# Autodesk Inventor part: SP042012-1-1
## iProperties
Created: 2012-04
Part Number: SP042012-1-1
Material: PVC-U
Document SubType Name: Modeling
Designer: Administrator
Density: 1.4 g/cm^3
Mass: 303.761 g
Surface Area: 2103.56 cm^2
Volume: 216.972 cm^3
Author: Administrator
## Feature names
1. Extrusion1
